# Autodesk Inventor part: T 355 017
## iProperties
Company: Mayer & Müller AG Schaltgeräte
Created: 2005-12
Part Number: T 355 017
Material: 2.0402.30
Document SubType Name: Modeling
Designer: I.Baliuc
Manufacturer: Standard
Standards Organization: Custom
Description: Bolzen
Density: 8.2 g/cm^3
HalbzeugNorm: DIN 1756
Zweck: Strombahn
Abmessung: Rd 10 - 96,5
Author: T.Messerschmitt
Keywords: 267031
Revision Number: 355017
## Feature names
1. Extrusion2
2. Extrusion3
3. Extrusion4
4. Spiegeln1 [Mirror]
